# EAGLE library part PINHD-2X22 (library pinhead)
PIN HEADER
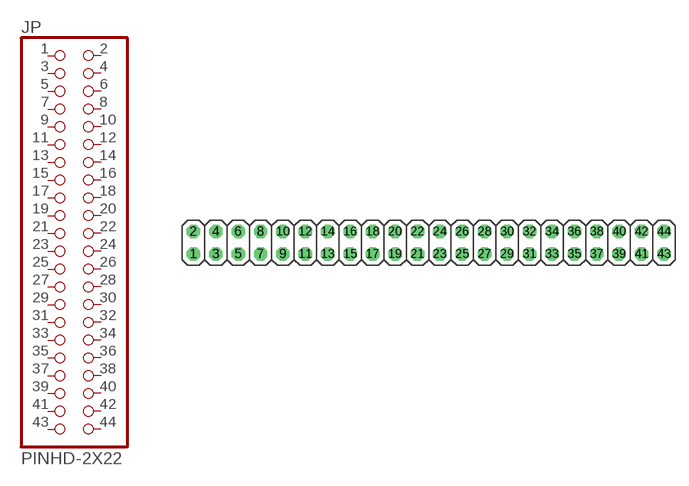
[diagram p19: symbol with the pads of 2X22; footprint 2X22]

Designator prefix JP

## PINHD-2X22  [2X22]
1  1  pas
2  2  pas
3  3  pas
4  4  pas
5  5  pas
6  6  pas
7  7  pas
8  8  pas
9  9  pas
10  10  pas
11  11  pas
12  12  pas
13  13  pas
14  14  pas
15  15  pas
16  16  pas
17  17  pas
18  18  pas
19  19  pas
20  20  pas
21  21  pas
22  22  pas
23  23  pas
24  24  pas
25  25  pas
26  26  pas
27  27  pas
28  28  pas
29  29  pas
30  30  pas
31  31  pas
32  32  pas
33  33  pas
34  34  pas
35  35  pas
36  36  pas
37  37  pas
38  38  pas
39  39  pas
40  40  pas
41  41  pas
42  42  pas
43  43  pas
44  44  pas

## Footprint 2X22 (pad centres in mm)
PIN HEADER
drill 1.016 octagon: 1 -25.4,-1.27; 2 -25.4,1.27; 3 -22.86,-1.27; 4 -22.86,1.27; 5 -20.32,-1.27; 6 -20.32,1.27; 7 -17.78,-1.27; 8 -17.78,1.27; 9 -15.24,-1.27; 10 -15.24,1.27; 11 -12.7,-1.27; 12 -12.7,1.27; 13 -10.16,-1.27; 14 -10.16,1.27; 15 -7.62,-1.27; 16 -7.62,1.27; 17 -5.08,-1.27; 18 -5.08,1.27; 19 -2.54,-1.27; 20 -2.54,1.27; 21 0,-1.27; 22 0,1.27; 23 2.54,-1.27; 24 2.54,1.27; 25 5.08,-1.27; 26 5.08,1.27; 27 7.62,-1.27; 28 7.62,1.27; 29 10.16,-1.27; 30 10.16,1.27; 31 12.7,-1.27; 32 12.7,1.27; 33 15.24,-1.27; 34 15.24,1.27; 35 17.78,-1.27; 36 17.78,1.27; 37 20.32,-1.27; 38 20.32,1.27; 39 22.86,-1.27; 40 22.86,1.27; 41 25.4,-1.27; 42 25.4,1.27; 43 27.94,-1.27; 44 27.94,1.27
